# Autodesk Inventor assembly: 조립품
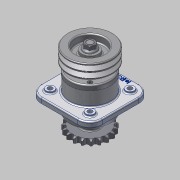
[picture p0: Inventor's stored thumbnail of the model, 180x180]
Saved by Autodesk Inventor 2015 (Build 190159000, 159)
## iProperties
Created: 2015-07
Part Number: 조립품
Document SubType Name: Assembly
Designer: AMC
Author: AMC
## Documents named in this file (12)
- C:\Users\AMC\Desktop\450735V1012\조립품.iam
- C:\Users\AMC\Desktop\450735V1012\본체.ipt
- C:\Users\AMC\Desktop\450735V1012\2-커버.ipt
- C:\Users\AMC\Desktop\450735V1012\3-축.ipt
- C:\Users\AMC\Desktop\450735V1012\4-V벨트풀리.ipt
- C:\Users\AMC\Desktop\450735V1012\5-체인 스프로킷.ipt
- C:\Users\AMC\Desktop\450735V1012\6-베어링 6206.ipt
- C:\Users\AMC\Desktop\450735V1012\7-부시.ipt
- C:\Users\AMC\Desktop\450735V1012\8-오일실 30x42.ipt
- C:\Users\AMC\Desktop\450735V1012\9-M16-너트.ipt
- C:\Users\AMC\Desktop\450735V1012\10-M6.ipt
- C:\Users\AMC\Desktop\450735V1012\11-키 6x6.ipt
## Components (22 placed, 10 different names)
1. 2-커버:1
2. 3-축:1
3. 4-V벨트풀리:1 — 각도:1
4. 5-체인 스프로킷:1 — 각도:2
5. 6-베어링 6206:1
6. 7-부시:1
7. 8-8-오일실 30x42:1
8. 9-M16 너트:1
9. 11-키 6x6:1 — 각도:1
10. 6-베어링 6206:2
11. 2-커버:2
12. 8-8-오일실 30x42:2
13. 11-키 6x6:2 — 각도:2
14. 9-M16 너트:2
15. 10-M6:2
16. 10-M6:3
17. 10-M6:4
18. 10-M6:5
19. 10-M6:1
20. 10-M6:6
21. 10-M6:7
22. 10-M6:8
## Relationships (2: Angle 2)
- 각도:1 [Angle]: 4-V벨트풀리:1 ↔ 11-키 6x6:1
- 각도:2 [Angle]: 5-체인 스프로킷:1 ↔ 11-키 6x6:2
